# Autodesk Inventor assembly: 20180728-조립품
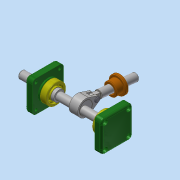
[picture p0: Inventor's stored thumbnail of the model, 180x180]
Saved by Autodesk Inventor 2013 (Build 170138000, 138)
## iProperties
Created: 2018-07
Part Number: 20180728-조립품
Document SubType Name: Assembly
Designer: dgall
Author: dgall
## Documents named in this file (11)
- C:\Users\dgall\Desktop\480707V1008\20180728-조립품.iam
- C:\Users\dgall\Desktop\480707V1008\20180728-본체.ipt
- C:\Users\dgall\Desktop\480707V1008\뒤커버.ipt
- C:\Users\dgall\Desktop\480707V1008\베어링 12x32x10.ipt
- C:\Users\dgall\Desktop\480707V1008\앞커버.ipt
- C:\Users\dgall\Desktop\480707V1008\편심축.ipt
- C:\Users\dgall\Desktop\480707V1008\고정핀 1.2x8.ipt
- C:\Users\dgall\Desktop\480707V1008\링크.ipt
- C:\Users\dgall\Desktop\480707V1008\부시.ipt
- C:\Users\dgall\Desktop\480707V1008\슬라이드.ipt
- C:\Users\dgall\Desktop\480707V1008\핀 5x18.ipt
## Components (3 placed, 3 different names)
1. 20180728-본체:1
2. 고정핀 1.2x8:1
3. 핀 5x18:1
